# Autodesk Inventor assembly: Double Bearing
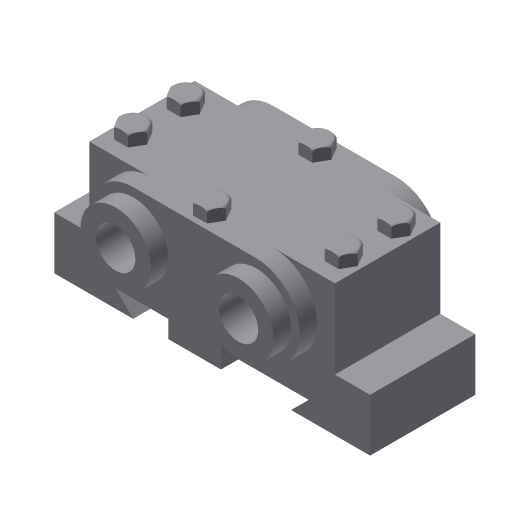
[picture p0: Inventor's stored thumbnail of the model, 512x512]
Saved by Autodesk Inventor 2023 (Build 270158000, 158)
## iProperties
Created: 2002-02
Part Number: Double Bearing
Document SubType Name: Assembly
Designer: ***
Control State: 0
Master: False
Checked Out: False
Shininess: 64.0
Length Units: 11269
Angle Units: 11279
Time Units: 11290
Mass Units: 11283
Length Display Precision: 3
Angle Display Precision: 2
Density: 0.0
Volumn: 0.0
Area: 0.0
PropertySet Name: Model Information
Author: ***
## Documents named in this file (5)
- D:\PROJECTS\Project 2022\Autodesk Inventor For Professional 2023\RESOURCES INVENTOR 2023\RESOURCES INVENTOR 2023\Inventor_2023_Part\Inventor_2023_Part\c12_Inv_2023_prt\fig-12-10 and 12-18\Double Bearing.iam
- D:\PROJECTS\Project 2022\Autodesk Inventor For Professional 2023\RESOURCES INVENTOR 2023\RESOURCES INVENTOR 2023\Inventor_2023_Part\Inventor_2023_Part\c12_Inv_2023_prt\fig-12-10 and 12-18\Base.ipt
- D:\PROJECTS\Project 2022\Autodesk Inventor For Professional 2023\RESOURCES INVENTOR 2023\RESOURCES INVENTOR 2023\Inventor_2023_Part\Inventor_2023_Part\c12_Inv_2023_prt\fig-12-10 and 12-18\Cap.ipt
- D:\PROJECTS\Project 2022\Autodesk Inventor For Professional 2023\RESOURCES INVENTOR 2023\RESOURCES INVENTOR 2023\Inventor_2023_Part\Inventor_2023_Part\c12_Inv_2023_prt\fig-12-10 and 12-18\Bushing.ipt
- D:\PROJECTS\Project 2022\Autodesk Inventor For Professional 2023\RESOURCES INVENTOR 2023\RESOURCES INVENTOR 2023\Inventor_2023_Part\Inventor_2023_Part\c12_Inv_2023_prt\fig-12-10 and 12-18\Bolt.ipt
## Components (10 placed, 4 different names)
1. Base:1 — Insert:1, Insert:2
2. Cap:1 — Insert:1, Insert:2, Insert:3, Insert:4, Insert:5, Insert:6
3. Bushing:1 — Insert:3
4. Bushing:2 — Insert:4
5. Bolt:1 — Insert:5
6. Bolt:6
7. Bolt:7
8. Bolt:8
9. Bolt:5 — Insert:6
10. Bolt:9
## Component patterns: Component Pattern 1 (4 elements), Component Pattern 2 (2 elements)
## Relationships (6: Insert 6)
- Insert:1: Base:1 ↔ Cap:1
- Insert:2: Base:1 ↔ Cap:1
- Insert:3: Cap:1 ↔ Bushing:1
- Insert:4: Cap:1 ↔ Bushing:2
- Insert:5: Cap:1 ↔ Bolt:1
- Insert:6: Cap:1 ↔ Bolt:5
